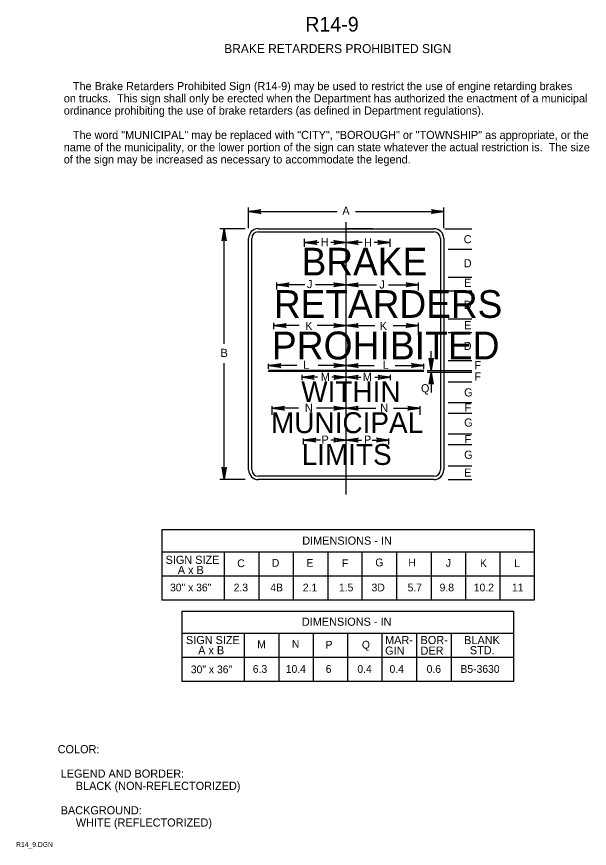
# Model space of a CAD drawing. Extents: x 0.013 to 0.188, y 0.004 to 0.259.
import ezdxf

# ---------------------------------------------------------------- set-up
doc = ezdxf.new("R2010")
doc.units = 0
for name, color, linetype in [('1', 7, 'Continuous'), ('11', 7, 'Continuous'), ('12', 7, 'Continuous'), ('2', 7, 'Continuous'), ('3', 7, 'Continuous')]:
    doc.layers.add(name, color=color, linetype=linetype)

# ---------------------------------------------------------------- blocks, each defined once
blk = doc.blocks.new('RARROW')
at = {"layer": '3'}
for p, q in [((-2.156, 0.285), (-2.2665, 0.384625)), ((-2.2665, 0.384625), (0, 0)), ((0, 0), (-2.2665, -0.379125)), ((-2.156, 0.285), (-2.075625, 0.12075)), ((0, 0), (-2.156, 0.285)), ((-2.14975, -0.2705), (0, 0)), ((-2.075625, 0.12075), (0, 0)), ((0, 0), (-2.074, -0.108)), ((-2.2665, -0.379125), (-2.14975, -0.2705)), ((-2.074, -0.108), (-2.14975, -0.2705))]:
    blk.add_line(p, q, dxfattribs=at)

msp = doc.modelspace()

# ---------------------------------------------------------------- linework, layer by layer
at = {"layer": '11'}
for p, q in [((0.08663, 0.19312), (0.14062, 0.19312)), ((0.08475, 0.12012), (0.08475, 0.19112)), ((0.14263, 0.19112), (0.14263, 0.12012)), ((0.14062, 0.11813), (0.08663, 0.11813))]:
    msp.add_line(p, q, dxfattribs=at)
for centre, radius, start, end in [((0.08669, 0.19119), 0.00194, 91.8476, 181.8476), ((0.14062, 0.19112), 0.002, 0, 90), ((0.08675, 0.12012), 0.002, 180, 270), ((0.14062, 0.12012), 0.002, 270, 0)]:
    msp.add_arc(centre, radius, start, end, dxfattribs=at)
at = {"layer": '12'}
for p, q in [((0.08987, 0.1505), (0.1375, 0.1505)), ((0.08987, 0.15038), (0.1375, 0.15038))]:
    msp.add_line(p, q, dxfattribs=at)
at = {"layer": '3'}
for p, q in [((0.08375, 0.19425), (0.08375, 0.20062)), ((0.08375, 0.19937), (0.11088, 0.19937)), ((0.1165, 0.19937), (0.14363, 0.19937)), ((0.14363, 0.19425), (0.14363, 0.20062)), ((0.08263, 0.19412), (0.07487, 0.19412)), ((0.07625, 0.15875), (0.07625, 0.19412)), ((0.08663, 0.19412), (0.14062, 0.19412)), ((0.11363, 0.1125), (0.11363, 0.19612)), ((0.12187, 0.19412), (0.11363, 0.19412)), ((0.144, 0.19412), (0.15225, 0.19412)), ((0.08375, 0.12012), (0.08375, 0.19112)), ((0.10088, 0.1885), (0.10088, 0.191)), ((0.10525, 0.18988), (0.10088, 0.18988)), ((0.11363, 0.18988), (0.109, 0.18988)), ((0.11863, 0.18988), (0.11363, 0.18988)), ((0.12713, 0.18988), (0.12225, 0.18988)), ((0.12713, 0.1885), (0.12713, 0.191)), ((0.14363, 0.19112), (0.14363, 0.12012)), ((0.145, 0.18788), (0.15225, 0.18788)), ((0.145, 0.17925), (0.15225, 0.17925)), ((0.09237, 0.1755), (0.09237, 0.17763)), ((0.101, 0.17688), (0.09237, 0.17688)), ((0.11363, 0.17688), (0.10425, 0.17688)), ((0.11363, 0.17688), (0.123, 0.17688)), ((0.12663, 0.17688), (0.13587, 0.17688)), ((0.13587, 0.17513), (0.13587, 0.17763)), ((0.145, 0.175), (0.15225, 0.175)), ((0.145, 0.1665), (0.15225, 0.1665)), ((0.0915, 0.16325), (0.0915, 0.16525)), ((0.09925, 0.16437), (0.0915, 0.16437)), ((0.11363, 0.16437), (0.10475, 0.16437)), ((0.11363, 0.16437), (0.1225, 0.16437)), ((0.12812, 0.16437), (0.13587, 0.16437)), ((0.13587, 0.1615), (0.13587, 0.16525)), ((0.145, 0.16225), (0.15225, 0.16225)), ((0.13975, 0.15063), (0.13975, 0.1565)), ((0.145, 0.15363), (0.15225, 0.15363)), ((0.07625, 0.11713), (0.07625, 0.15288)), ((0.08987, 0.15113), (0.08987, 0.15263)), ((0.0985, 0.15213), (0.08987, 0.15213)), ((0.1375, 0.15063), (0.08987, 0.15063)), ((0.11363, 0.15213), (0.10512, 0.15213)), ((0.11363, 0.15213), (0.12225, 0.15213)), ((0.12875, 0.15213), (0.1375, 0.15213)), ((0.1375, 0.15113), (0.1375, 0.15263)), ((0.1385, 0.15063), (0.15225, 0.15063)), ((0.08987, 0.15038), (0.08987, 0.1505)), ((0.1375, 0.15025), (0.08987, 0.15025)), ((0.10013, 0.14763), (0.10013, 0.14925)), ((0.10487, 0.1485), (0.10013, 0.1485)), ((0.11363, 0.1485), (0.10925, 0.1485)), ((0.11363, 0.1485), (0.11813, 0.1485)), ((0.1225, 0.1485), (0.12725, 0.1485)), ((0.12725, 0.14763), (0.12725, 0.14925)), ((0.1375, 0.15038), (0.1375, 0.1505)), ((0.1385, 0.15013), (0.15225, 0.15013)), ((0.13975, 0.15013), (0.13975, 0.14388)), ((0.145, 0.14713), (0.15225, 0.14713)), ((0.145, 0.14075), (0.15225, 0.14075)), ((0.091, 0.137), (0.091, 0.13962)), ((0.099, 0.139), (0.091, 0.139)), ((0.11363, 0.139), (0.10462, 0.139)), ((0.11363, 0.139), (0.12275, 0.139)), ((0.12825, 0.139), (0.13637, 0.139)), ((0.13637, 0.137), (0.13637, 0.13962)), ((0.145, 0.1375), (0.15225, 0.1375)), ((0.145, 0.13112), (0.15225, 0.13112)), ((0.10063, 0.12788), (0.10063, 0.12975)), ((0.10575, 0.12925), (0.10063, 0.12925)), ((0.11363, 0.12925), (0.109, 0.12925)), ((0.11363, 0.12925), (0.11838, 0.12925)), ((0.12162, 0.12925), (0.12675, 0.12925)), ((0.12675, 0.12788), (0.12675, 0.12975)), ((0.145, 0.12788), (0.15225, 0.12788)), ((0.145, 0.12137), (0.15225, 0.12137)), ((0.08263, 0.11713), (0.07487, 0.11713)), ((0.14062, 0.11713), (0.08663, 0.11713)), ((0.12087, 0.11713), (0.11363, 0.11713)), ((0.145, 0.11713), (0.15225, 0.11713)), ((0.05713, 0.10175), (0.17137, 0.10175)), ((0.05713, 0.10175), (0.05713, 0.08013)), ((0.17137, 0.10175), (0.17137, 0.08013)), ((0.17137, 0.09488), (0.05713, 0.09488)), ((0.07625, 0.09496), (0.07625, 0.08021)), ((0.08688, 0.09488), (0.08688, 0.08013)), ((0.09738, 0.09488), (0.09738, 0.08013)), ((0.108, 0.09488), (0.108, 0.08013)), ((0.1185, 0.09488), (0.1185, 0.08013)), ((0.12912, 0.09488), (0.12912, 0.08013)), ((0.13975, 0.09488), (0.13975, 0.08013)), ((0.15025, 0.09488), (0.15025, 0.08013)), ((0.16087, 0.09488), (0.16087, 0.08013)), ((0.17137, 0.0875), (0.05713, 0.0875)), ((0.17137, 0.08013), (0.05713, 0.08013)), ((0.06325, 0.07675), (0.06325, 0.05513)), ((0.06325, 0.07675), (0.165, 0.07675)), ((0.165, 0.07675), (0.165, 0.05513)), ((0.165, 0.06988), (0.06325, 0.06988)), ((0.08235, 0.06997), (0.08235, 0.05516)), ((0.093, 0.06988), (0.093, 0.05513)), ((0.1035, 0.06988), (0.1035, 0.05513)), ((0.11413, 0.06988), (0.11413, 0.05513)), ((0.1246, 0.06997), (0.1246, 0.05516)), ((0.13522, 0.06997), (0.13522, 0.05516)), ((0.14585, 0.06997), (0.14585, 0.05516)), ((0.165, 0.0625), (0.06325, 0.0625)), ((0.165, 0.05513), (0.06325, 0.05513))]:
    msp.add_line(p, q, dxfattribs=at)
for centre, radius, start, end in [((0.08669, 0.19119), 0.00294, 91.2189, 181.2189), ((0.14062, 0.19112), 0.003, 0, 90), ((0.08675, 0.12012), 0.003, 180, 270), ((0.14062, 0.12012), 0.003, 270, 0)]:
    msp.add_arc(centre, radius, start, end, dxfattribs=at)

# ---------------------------------------------------------------- block references
at = {"layer": '3', "xscale": 0.0016545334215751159, "yscale": 0.0016366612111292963}
for p, rotation in [((0.08375, 0.19937), 180), ((0.07625, 0.19412), 90), ((0.10088, 0.18988), 180), ((0.11363, 0.18988), 180), ((0.09237, 0.17688), 180), ((0.11363, 0.17688), 180), ((0.0915, 0.16437), 180), ((0.11363, 0.16437), 180), ((0.13975, 0.15063), -90), ((0.08987, 0.15213), 180), ((0.11363, 0.15213), 180), ((0.10013, 0.1485), 180), ((0.11363, 0.1485), 180), ((0.13975, 0.15013), 90), ((0.091, 0.139), 180), ((0.11363, 0.139), 180), ((0.10063, 0.12925), 180), ((0.11363, 0.12925), 180), ((0.07625, 0.11713), -90)]:
    msp.add_blockref('RARROW', p, dxfattribs=dict(at, rotation=rotation))
for p in [(0.14363, 0.19937), (0.11363, 0.18988), (0.12713, 0.18988), (0.11363, 0.17688), (0.13587, 0.17688), (0.11363, 0.16437), (0.13587, 0.16437), (0.11363, 0.15213), (0.1375, 0.15213), (0.11363, 0.1485), (0.12725, 0.1485), (0.11363, 0.139), (0.13637, 0.139), (0.11363, 0.12925), (0.12675, 0.12925)]:
    msp.add_blockref('RARROW', p, dxfattribs=at)

# ---------------------------------------------------------------- texts
at = {"layer": '1'}
for s, height, p in [('R14-9', 0.0045, (0.10113, 0.25462)), ('BRAKE RETARDERS PROHIBITED SIGN', 0.0027503, (0.07625, 0.248)), ('COLOR:', 0.0025, (0.02513, 0.03313)), (' LEGEND AND BORDER:', 0.0024998, (0.02513, 0.02563)), ('      BLACK (NON-REFLECTORIZED)', 0.0024998, (0.02513, 0.02188)), (' BACKGROUND:', 0.0024998, (0.02513, 0.01438)), ('      WHITE (REFLECTORIZED)', 0.0024998, (0.02513, 0.01063)), ('R14_9.DGN', 0.0015, (0.01238, 0.00438))]:
    msp.add_text(s, height=height, dxfattribs=at).set_placement(p)
at = {"layer": '12'}
for s, height, p in [('BRAKE', 0.0085, (0.1, 0.17975)), ('RETARDERS', 0.0085, (0.0915, 0.16675)), ('PROHIBITED', 0.008549, (0.09087, 0.154)), ('WITHIN', 0.006413, (0.09988, 0.14088)), ('MUNICIPAL', 0.006413, (0.09062, 0.13137)), ('LIMITS', 0.006413, (0.1, 0.12162))]:
    msp.add_text(s, height=height, dxfattribs=at).set_placement(p)
at = {"layer": '2'}
for s, height, p in [('   The Brake Retarders Prohibited Sign (R14-9) may be used to restrict the use of engine retarding brakes', 0.00249975, (0.027, 0.23663)), ('on trucks.  This sign shall only be erected when the Department has authorized the enactment of a municipal', 0.00249975, (0.027, 0.23288)), ('ordinance prohibiting the use of brake retarders (as defined in Department regulations).', 0.0024998, (0.027, 0.22913)), ('   The word "MUNICIPAL" may be replaced with "CITY", "BOROUGH" or "TOWNSHIP" as appropriate, or the', 0.0024998, (0.027, 0.22163)), ('name of the municipality, or the lower portion of the sign can state whatever the actual restriction is.  The size', 0.00249975, (0.027, 0.21788)), ('of the sign may be increased as necessary to accommodate the legend.', 0.0024998, (0.027, 0.21413))]:
    msp.add_text(s, height=height, dxfattribs=at).set_placement(p)
at = {"layer": '3'}
for s, height, p in [('A', 0.0025, (0.1125, 0.19837)), ('C', 0.0025, (0.14975, 0.18963)), ('H', 0.0025, (0.10587, 0.18875)), ('H', 0.0025, (0.11913, 0.18863)), ('D', 0.0025, (0.14975, 0.18225)), ('E', 0.0025, (0.14988, 0.17625)), ('J', 0.0025, (0.10163, 0.17588)), ('J', 0.0025, (0.12387, 0.17575)), ('D', 0.0025, (0.14975, 0.1695)), ('K', 0.0025, (0.10113, 0.163)), ('K', 0.0025, (0.124, 0.163)), ('E', 0.0025, (0.14988, 0.16325)), ('D', 0.0025, (0.14975, 0.15688)), ('B', 0.0025, (0.07512, 0.15475)), ('L', 0.0025, (0.1005, 0.15113)), ('L', 0.0025, (0.12487, 0.15113)), ('F', 0.0025, (0.153, 0.151)), ('M', 0.0025, (0.10587, 0.14738)), ('M', 0.0025, (0.11875, 0.14738)), ('F', 0.0025, (0.153, 0.1475)), ('Q', 0.0025, (0.13662, 0.14388)), ('G', 0.0025, (0.14988, 0.14263)), ('F', 0.0025, (0.15, 0.138)), ('N', 0.0025, (0.101, 0.13787)), ('N', 0.0025, (0.12412, 0.13787)), ('G', 0.0025, (0.14988, 0.13337)), ('P', 0.0025, (0.10612, 0.12812)), ('P', 0.0025, (0.11913, 0.12812)), ('F', 0.0025, (0.15, 0.12825)), ('G', 0.0025, (0.14988, 0.1235)), ('E', 0.0025, (0.14988, 0.118)), ('DIMENSIONS - IN', 0.0024998, (0.1002, 0.09713)), ('SIGN SIZE', 0.0025, (0.05825, 0.09125)), ('C', 0.00238, (0.08025, 0.09025)), ('D', 0.00238, (0.09087, 0.09037)), ('E', 0.00238, (0.1015, 0.09037)), ('F', 0.00238, (0.11238, 0.09025)), ('G', 0.00238, (0.12262, 0.0905)), ('H', 0.00238, (0.13275, 0.0905)), ('J', 0.00238, (0.14425, 0.09037)), ('K', 0.00238, (0.15475, 0.09025)), ('L', 0.00238, (0.16525, 0.09025)), ('A x B', 0.0025, (0.062, 0.08812)), ('30" x 36"', 0.002375, (0.05962, 0.08281)), ('2.3', 0.002375, (0.07915, 0.08281)), ('4B', 0.002375, (0.09039, 0.08281)), ('2.1', 0.002375, (0.10037, 0.08281)), ('1.5', 0.002375, (0.11146, 0.08281)), ('3D', 0.002375, (0.12147, 0.08281)), ('5.7', 0.002375, (0.13253, 0.08281)), ('9.8', 0.002375, (0.14236, 0.08281)), ('10.2', 0.002375, (0.15283, 0.08281)), ('11', 0.002375, (0.16455, 0.08281)), ('DIMENSIONS - IN', 0.0024998, (0.10008, 0.07225)), ('SIGN SIZE', 0.0025, (0.0645, 0.06663)), ('MAR-', 0.0025, (0.12563, 0.06663)), ('BOR-', 0.0025, (0.1365, 0.06663)), ('BLANK', 0.0025, (0.14988, 0.06663)), ('M', 0.00238, (0.08638, 0.06538)), ('N', 0.00238, (0.097, 0.0655)), ('P', 0.00238, (0.10737, 0.06525)), ('Q', 0.00238, (0.1185, 0.06525)), ('A x B', 0.0025, (0.06825, 0.0635)), ('GIN', 0.0025, (0.12563, 0.06338)), ('DER', 0.0025, (0.1365, 0.06338)), ('STD.', 0.0025, (0.15163, 0.0635)), ('30" x 36"', 0.002375, (0.066, 0.05769)), ('6.3', 0.002375, (0.08503, 0.05781)), ('10.4', 0.002375, (0.09514, 0.05781)), ('6', 0.00238, (0.1074, 0.05781)), ('0.4', 0.002375, (0.11711, 0.05781)), ('0.4', 0.002375, (0.12698, 0.05781)), ('0.6', 0.002375, (0.13837, 0.05781)), ('B5-3630', 0.002375, (0.14875, 0.05781))]:
    msp.add_text(s, height=height, dxfattribs=at).set_placement(p)

doc.saveas('drawing.dxf')
